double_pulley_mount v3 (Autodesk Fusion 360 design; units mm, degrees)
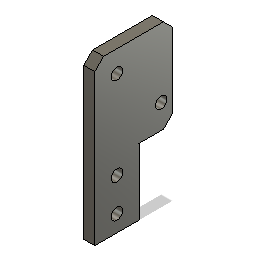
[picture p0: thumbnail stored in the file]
sketch "Sketch1" plane through (0, 0, 0) normal (1, 0, 0) x axis (0, 0, -1)
  line L1 (25, 21) -> (-10, 21)
  line L2 (25, -21) -> (25, 21)
  line L3 (-10, -21) -> (25, -21)
  line L4 (-10, 21) -> (-10, -21)
  line L5 (25, 0) -> (-10, 0)
  line L6 (0, 2.5) -> (0, 20)
  line L7 (0, -55) -> (0, 2.5)
  line L8 (10, -21) -> (-10, -21)
  line L9 (10, -51) -> (10, -21)
  line L10 (-10, -51) -> (10, -51)
  line L11 (-10, -21) -> (-10, -51)
  line L12 (10, -20) -> (10, -21)
  line L13 (10, 30) -> (10, -20)
  line L14 (-10, 30) -> (-10, -21)
  line L15 (20, 32.0321) -> (20, -21)
  line L16 (-20, 30) -> (-20, -21)
  circle C1 centre (20, -10) radius 2.6
  circle C2 centre (0, 11.25) radius 2.6
  circle C3 centre (0, -28.5) radius 2.6
  circle C4 centre (0, -43.5) radius 2.6
  point P6 (-10, 0)
  point P7 (25, 0)
  point P4 (25, -21)
  point P10 (25, -21)
  point P9 (0, 2.5)
  point P11 (0, 2.5)
  point P13 (-10, -21)
  point P20 (20, -21)
  point P22 (-20, -21)
  point P24 (20, -10)
  point P25 (0, 11.25)
  point P26 (0, -28.5)
  point P27 (0, -43.5)
  point P2 (-10, 21)
  point P3 (25, 21)
  point P15 (10, -51)
  point P16 (-10, -51)
  horizontal L1
  vertical L2
  vertical L4
  midpoint L4 P6
  midpoint L2 P7
  coincident P4 P10
  coincident P9 P11
  perpendicular L5 L7
  horizontal L8
  vertical L9
  horizontal L10
  vertical L11
  coincident L3 P13
  perpendicular L3 L12
  perpendicular L3 L13
  perpendicular L1 L14
  coincident L3 P20
  perpendicular L1 L15
  coincident L3 P22
  perpendicular L1 L16
  coincident L15 P24
  midpoint L6 P25
  coincident L7 P26
  coincident L7 P27
  dimension "d1" distance P2 P3 = 35
  dimension "d4" distance P3 P4 = 42
  dimension "d36" distance P15 P16 = 20
  dimension "d37" distance P13 P16 = 30
  dimension "d38" distance L14 L16 = 10
  dimension "d39" distance L13 L15 = 10
  dimension "d40" diameter C1 = 5.2
  dimension "d42" diameter C2 = 5.2
  dimension "d43" diameter C3 = 5.2
  dimension "d44" diameter C4 = 5.2
  dimension "d45" distance P15 P27 = 7.5
  dimension "d46" distance L3 P26 = 7.5
extrude "Extrude4" new body sketch "Sketch1" profile of L1 L2 L3 L4 L8 L9 L10 L11 C1 C2 C3 C4 along normal blind 5
chamfer "Chamfer2" distance 4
